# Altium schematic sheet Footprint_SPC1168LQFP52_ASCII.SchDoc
size A4; 项目编号: SPSZ2023-052501A; 项目名称: 三相PFC-2.2KW压机+700W风机
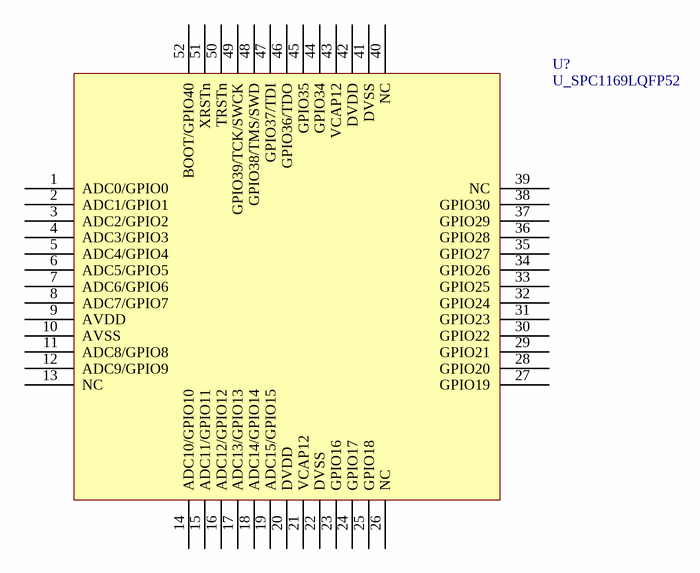
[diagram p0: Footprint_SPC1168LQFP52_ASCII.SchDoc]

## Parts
U?  U_SPC1169LQFP52

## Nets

Not connected (* = marked no-connect by the designer): U? 1(ADC0/GPIO0) 2(ADC1/GPIO1) 3(ADC2/GPIO2) 4(ADC3/GPIO3) 5(ADC4/GPIO4) 6(ADC5/GPIO5) 7(ADC6/GPIO6) 8(ADC7/GPIO7) 9(AVDD) 10(AVSS) 11(ADC8/GPIO8) 12(ADC9/GPIO9) 13(NC) 14(ADC10/GPIO10) 15(ADC11/GPIO11) 16(ADC12/GPIO12) 17(ADC13/GPIO13) 18(ADC14/GPIO14) 19(ADC15/GPIO15) 20(DVDD) 21(VCAP12) 22(DVSS) 23(GPIO16) 24(GPIO17) 25(GPIO18) 26(NC) 27(GPIO19) 28(GPIO20) 29(GPIO21) 30(GPIO22) 31(GPIO23) 32(GPIO24) 33(GPIO25) 34(GPIO26) 35(GPIO27) 36(GPIO28) 37(GPIO29) 38(GPIO30) 39(NC) 40(NC) 41(DVSS) 42(DVDD) 43(VCAP12) 44(GPIO34) 45(GPIO35) 46(GPIO36/TDO) 47(GPIO37/TDI) 48(GPIO38/TMS/SWD) 49(GPIO39/TCK/SWCK) 50(TRSTn) 51(XRSTn) 52(BOOT/GPIO40)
